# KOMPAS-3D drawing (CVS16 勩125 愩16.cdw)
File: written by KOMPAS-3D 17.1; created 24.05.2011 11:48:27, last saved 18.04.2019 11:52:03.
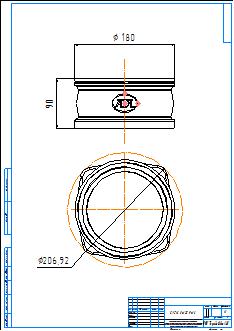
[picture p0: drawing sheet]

Title block, sheet 1: name: CVS16 Ду125 Ру16; material: Внимание! Данный продукт является объектом авторского права ООО «Торговый Дом АДЛ». / Запрещается изменение, копирование, распространение / (в том числе путем копирования на другие сайты и ресурсы в Интернете) / или любое иное использование информации и объектов без предварительного / согласия правообладателя (ООО «Торговый Дом АДЛ»).; scale: 1:1; sheets: 1; organisation: ООО "Торговый дом АДЛ"; sheet format: A2; stored path: \\adlc.lan\data\АДЛ_ПКД\3D-модели\ADL production\Клапаны обратные ГРАНЛОК\CVS16\KOMPAS 2D\CVS16 Ду125 Ру16.cdw

Views: Спереди 1, Проекционный вид 2
Dimensions and other numbers on the sheet: 180; 90; 206,92; 1:1; 1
